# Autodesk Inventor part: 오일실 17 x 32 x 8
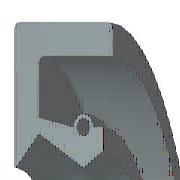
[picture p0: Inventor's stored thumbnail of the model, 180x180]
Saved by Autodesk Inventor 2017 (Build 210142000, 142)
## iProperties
IsCustomPart: 1
Created: 2012-02
Part Number: 오일실 17 x 32 x 8
Material: 고무
Description: 오일-실
Document SubType Name: Modeling
Standard: KS B 2804
Designer: mduedu
Standards Organization: KS
Language: ko-KR
Size Designation: D - 17 32 8
Categories: <MemberInstance><Categories><Category DisplayName="샤프트 부품" InternalName="7f7aeb1f-a693-4053-b835-cee3144e0d98" Mnemonic="SHFT"><Category DisplayName="실링" Intern
Density: 0.93 g/cm^3
Appearance: 고무 - 검은색 - 버전 1.1
Author: mduedu
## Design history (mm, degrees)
revolve "본체" stored, may be unused: angle "d17" = 90 deg
revolve "스프링1" stored, may be unused: angle "d18" = 90 deg
body "Solid1"
sketch "스케치1"
  geometry: L1 (0, 16)-(8, 16); L2 (8, 14.25)-(1.75, 14.25); L3 (1.75, 10.25)-(4.9, 8.5); L4 (4.9, 8.5)-(0, 8.5); L5 (0, 0)-(9.586, 0) reference; L6 (4.9, 8.5)-(6.3, 9.375); L7 (0, 18)-(0, -3) reference; L8 (-1.941, 0)-(11.507, 0) reference; L9 (4.2, 10.6)-(1.75, 11.21); L10 (1.75, 11.21)-(1.75, 14.25); L11 (0, 16)-(0, 8.588); L12 (4.9, 8.5)-(0, 8.5); L13 (1.75, 10.25)-(0.152, 8.528); L14 (8, 16)-(8, 14.25); L15 (5.6, 10.6)-(6.3, 10.6); L16 (6.3, 10.6)-(6.3, 9.375); C1 r 0.455 at (4.9, 10.6); A1 r 0.7 centre (4.9, 10.6) between (5.6, 10.6) and (4.2, 10.6); A2 r 0.088 centre (0.088, 8.588) between (0, 8.588) and (0.152, 8.528); 1 further point
  constraints: 28 end point, 5 horizontal alignment, 5 point on line, 4 point on circle, 4 vertical alignment, 3 centre point, 3 tangent, 2 collinear, 2 horizontal, 2 perpendicular, 1 coincident, 1 parallel
  dimensions: "d0" = 32 diameter of L1 L5 (= SD2); "d1" = 1.75 distance of L1.end L2.start (= SD); "d2" = 0.91 diameter of C1 (= SPDI); "d3" = 1.4 diameter of A1 (= SPDA); "d4" = 17 diameter of L3.end L5 (= NND); "d5" = 20.5 diameter of L3.start L5 (= TKDM); "d7" = 22.42 diameter of L9.end L5 (= TKDM + 0.24 x SWDT); "d8" = 1.75 distance between parallel lines of L11 L10 (= SD); "d9" = 4.9 distance from line of L11 C1.centre (= SPDST); "d10" = 21.2 diameter of C1.centre L5 (= HLDM); "d11" = 0.0875 radius of A2 (= 0.25 x LAB); "d12" = 6.3 distance between parallel lines of L11 L16 (= SDI); "d13" = 18.75 diameter of L6.end L5 (= ABDM); "d14" = 8 distance from line of L11 L1.end (= SWDT)
fillet "모깎기1" dims "d6" = 0.3 (= RR)
other parameters: "SD2" = 32 [user parameter; used in 1 equation term], "SWDT" = 8 [user parameter; used in 2 equation terms], "RR" = 0.3 [user parameter; used in 1 equation term], "SD" = 1.75 [user parameter; used in 2 equation terms], "NND" = 17 [user parameter; used in 1 equation term], "SPDA" = 1.4 [user parameter; used in 1 equation term], "SPDI" = 0.91 [user parameter; used in 1 equation term], "TKDM" = 20.5 [user parameter; used in 2 equation terms], "HLDM" = 21.2 [user parameter; used in 1 equation term], "ABDM" = 18.75 [user parameter; used in 1 equation term], "SDI" = 6.3 [user parameter; used in 1 equation term], "SPDST" = 4.9 [user parameter; used in 1 equation term], "LAB" = 0.35 [user parameter; used in 1 equation term], "d15" = 0, "d16" = 0, "d19" = 0
